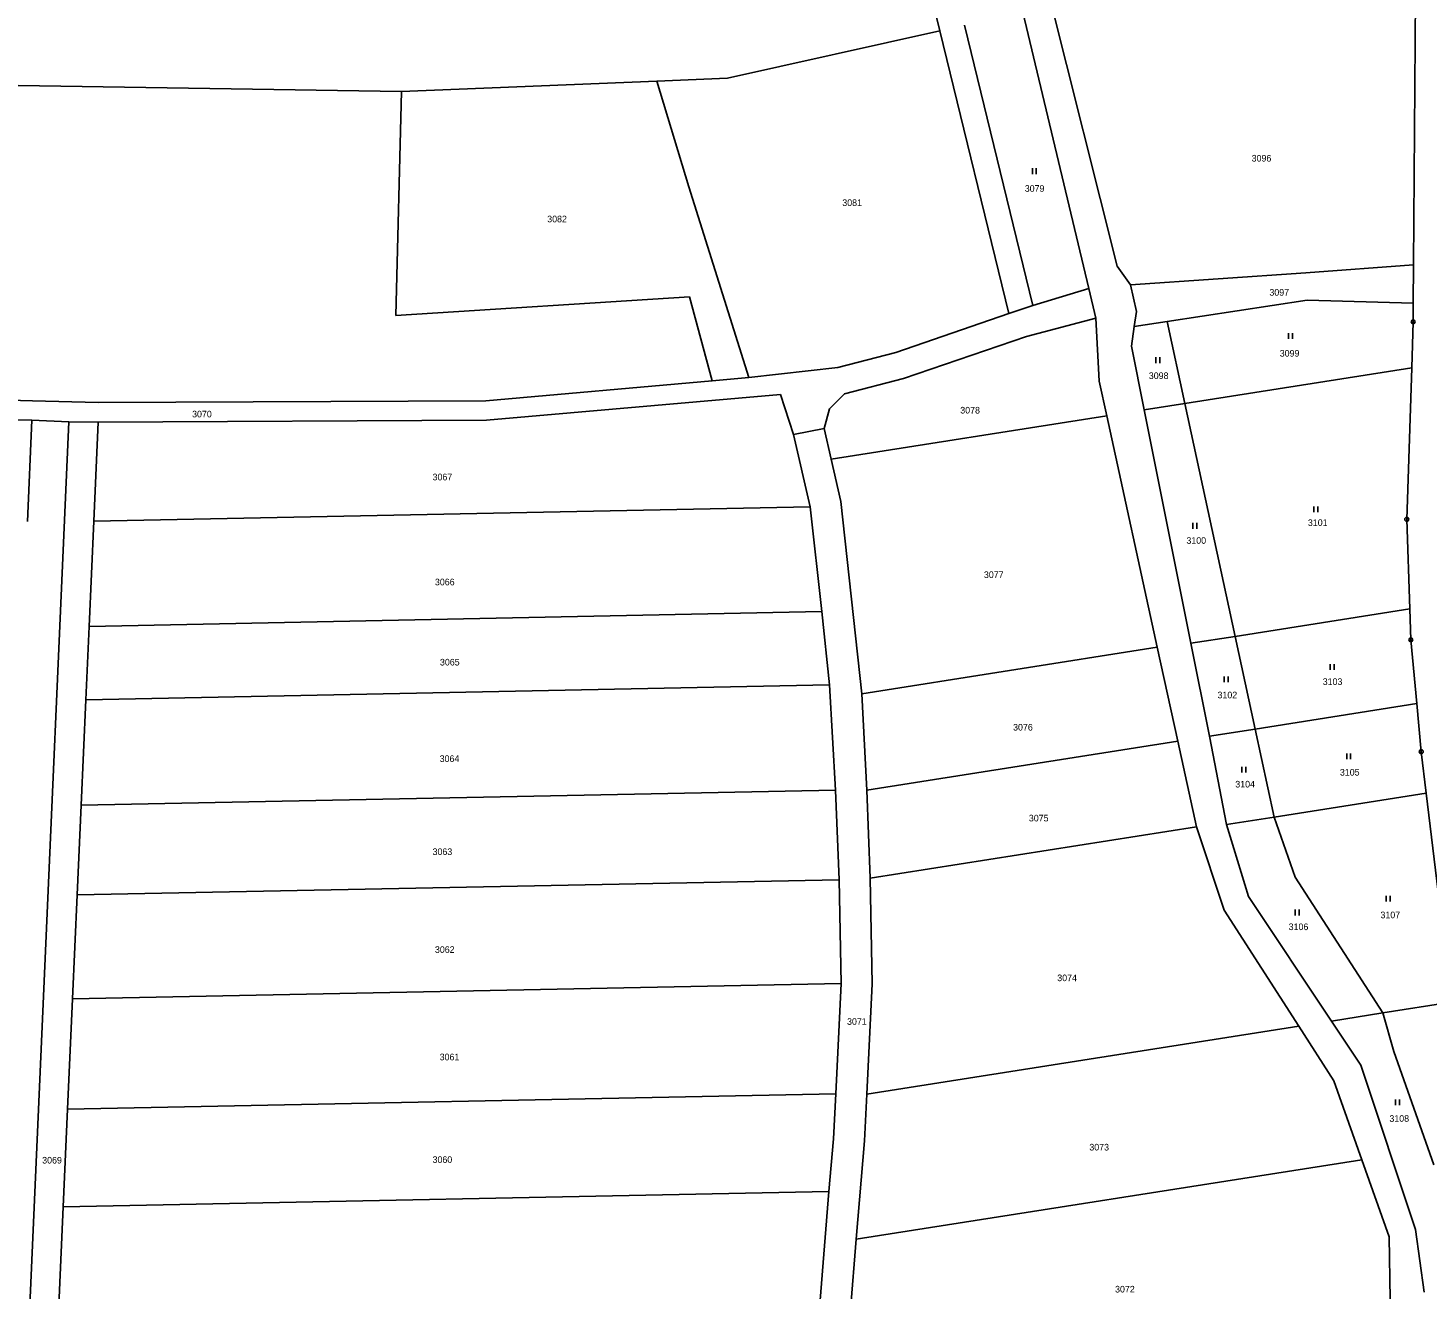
# Model space of a CAD drawing. Extents: x -618848 to -615803, y -1044450 to -1042254.
# Drawn here: x -617398.4 to -617038.7, y -1042756.5 to -1042432.5 of the extents above; entities that cross this region are included whole.
import ezdxf

# ---------------------------------------------------------------- set-up
doc = ezdxf.new("R2010")
doc.units = 0
doc.header["$LTSCALE"] = 0.68
for name, color, linetype, lineweight in [('1', 7, 'Continuous', 25), ('3', 7, 'Continuous', 25), ('8', 7, 'Continuous', 25)]:
    doc.layers.add(name, color=color, linetype=linetype, lineweight=lineweight)
doc.layers.add('2', color=7, linetype='Continuous')

msp = doc.modelspace()

# ---------------------------------------------------------------- linework, layer by layer
at = {"layer": '1'}
for p, q in [((-617164.1, -1042433.17), (-617176, -1042384.38)), ((-617041.82, -1042420.28), (-617042.37, -1042493.33)), ((-617136.12, -1042423.72), (-617118.55, -1042493.62)), ((-617157.76, -1042431.75), (-617140.2, -1042503.76)), ((-617125.82, -1042499.42), (-617142.76, -1042428.39)), ((-617218.65, -1042445.37), (-617164.1, -1042433.17)), ((-617146.38, -1042505.85), (-617164.1, -1042433.17)), ((-617302.39, -1042448.75), (-617236.84, -1042446.1)), ((-617236.84, -1042446.1), (-617218.65, -1042445.37)), ((-617236.84, -1042446.1), (-617228.59, -1042473.3)), ((-617465.98, -1042446.3), (-617302.39, -1042448.75)), ((-617303.82, -1042506.31), (-617302.39, -1042448.75)), ((-617228.59, -1042473.3), (-617213.14, -1042522.3)), ((-617118.55, -1042493.62), (-617115.07, -1042498.46)), ((-617115.07, -1042498.46), (-617070.06, -1042495.35)), ((-617070.06, -1042495.35), (-617042.37, -1042493.33)), ((-617042.37, -1042493.33), (-617042.45, -1042503.13)), ((-617140.2, -1042503.76), (-617125.82, -1042499.42)), ((-617124, -1042506.99), (-617125.82, -1042499.42)), ((-617115.07, -1042498.46), (-617113.6, -1042505.32)), ((-617228.38, -1042501.51), (-617303.82, -1042506.31)), ((-617222.59, -1042523.13), (-617228.38, -1042501.51)), ((-617140.2, -1042503.76), (-617146.38, -1042505.85)), ((-617069.68, -1042502.39), (-617105.66, -1042507.88)), ((-617042.45, -1042503.13), (-617069.68, -1042502.39)), ((-617042.45, -1042503.13), (-617042.48, -1042507.96)), ((-617175.43, -1042515.81), (-617146.38, -1042505.85)), ((-617141.86, -1042511.7), (-617124, -1042506.99)), ((-617123.16, -1042523.22), (-617124, -1042506.99)), ((-617113.6, -1042505.32), (-617114.15, -1042509.18)), ((-617114.15, -1042509.18), (-617114.86, -1042514.19)), ((-617105.66, -1042507.88), (-617114.15, -1042509.18)), ((-617101.11, -1042528.93), (-617105.66, -1042507.88)), ((-617042.48, -1042507.96), (-617042.86, -1042519.77)), ((-617173.41, -1042522.51), (-617141.86, -1042511.7)), ((-617114.86, -1042514.19), (-617111.59, -1042530.58)), ((-617190.33, -1042519.7), (-617175.43, -1042515.81)), ((-617213.14, -1042522.3), (-617190.33, -1042519.7)), ((-617101.11, -1042528.93), (-617042.86, -1042519.77)), ((-617042.86, -1042519.77), (-617044.13, -1042558.72)), ((-617222.59, -1042523.13), (-617280.75, -1042528.24)), ((-617213.14, -1042522.3), (-617222.59, -1042523.13)), ((-617188.56, -1042526.47), (-617173.41, -1042522.51)), ((-617121.22, -1042532.1), (-617123.16, -1042523.22)), ((-617397.22, -1042528.23), (-617515.35, -1042525.72)), ((-617380.36, -1042528.71), (-617397.22, -1042528.23)), ((-617280.75, -1042528.24), (-617380.36, -1042528.71)), ((-617280.52, -1042533.23), (-617205.06, -1042526.61)), ((-617205.06, -1042526.61), (-617201.67, -1042536.89)), ((-617192.45, -1042530.32), (-617188.56, -1042526.47)), ((-617111.59, -1042530.58), (-617101.11, -1042528.93)), ((-617088.23, -1042588.79), (-617101.11, -1042528.93)), ((-617497.67, -1042531.09), (-617397.33, -1042533.23)), ((-617193.81, -1042535.4), (-617192.45, -1042530.32)), ((-617121.22, -1042532.1), (-617192.03, -1042543.23)), ((-617108.24, -1042591.6), (-617121.22, -1042532.1)), ((-617111.59, -1042530.58), (-617099.62, -1042590.58)), ((-617397.33, -1042533.23), (-617398.46, -1042559.28)), ((-617397.33, -1042533.23), (-617387.84, -1042533.65)), ((-617394.98, -1042694.91), (-617387.84, -1042533.65)), ((-617387.84, -1042533.65), (-617380.34, -1042533.71)), ((-617381.47, -1042559.16), (-617380.34, -1042533.71)), ((-617380.34, -1042533.71), (-617280.52, -1042533.23)), ((-617201.67, -1042536.89), (-617193.81, -1042535.4)), ((-617192.03, -1042543.23), (-617193.81, -1042535.4)), ((-617201.67, -1042536.89), (-617197.44, -1042555.47)), ((-617192.03, -1042543.23), (-617189.55, -1042554.13)), ((-617189.55, -1042554.13), (-617184.17, -1042603.54)), ((-617197.44, -1042555.47), (-617381.47, -1042559.16)), ((-617194.37, -1042582.43), (-617197.44, -1042555.47)), ((-617381.47, -1042559.16), (-617382.67, -1042586.22)), ((-617044.13, -1042558.72), (-617043.35, -1042581.72)), ((-617382.67, -1042586.22), (-617194.37, -1042582.43)), ((-617194.37, -1042582.43), (-617192.47, -1042601.23)), ((-617043.35, -1042581.72), (-617088.23, -1042588.79)), ((-617043.35, -1042581.72), (-617043.08, -1042589.68)), ((-617383.51, -1042605.06), (-617382.67, -1042586.22)), ((-617099.62, -1042590.58), (-617088.23, -1042588.79)), ((-617083.1, -1042612.6), (-617088.23, -1042588.79)), ((-617043.08, -1042589.68), (-617041.55, -1042606.07)), ((-617184.17, -1042603.54), (-617108.24, -1042591.6)), ((-617102.98, -1042615.74), (-617108.24, -1042591.6)), ((-617099.62, -1042590.58), (-617094.85, -1042614.46)), ((-617192.47, -1042601.23), (-617383.51, -1042605.06)), ((-617190.9, -1042628.33), (-617192.47, -1042601.23)), ((-617184.17, -1042603.54), (-617182.86, -1042628.29)), ((-617383.51, -1042605.06), (-617384.7, -1042632.21)), ((-617083.1, -1042612.6), (-617041.55, -1042606.07)), ((-617041.55, -1042606.07), (-617040.41, -1042618.43)), ((-617094.85, -1042614.46), (-617083.1, -1042612.6)), ((-617094.85, -1042614.46), (-617090.4, -1042637.17)), ((-617078.2, -1042635.26), (-617083.1, -1042612.6)), ((-617182.86, -1042628.29), (-617102.98, -1042615.74)), ((-617098.18, -1042637.73), (-617102.98, -1042615.74)), ((-617040.41, -1042618.43), (-617039.11, -1042629.12)), ((-617384.7, -1042632.21), (-617190.9, -1042628.33)), ((-617190.9, -1042628.33), (-617189.97, -1042651.34)), ((-617181.99, -1042650.9), (-617182.86, -1042628.29)), ((-617078.2, -1042635.26), (-617039.11, -1042629.12)), ((-617039.11, -1042629.12), (-617034.33, -1042668.64)), ((-617385.72, -1042655.25), (-617384.7, -1042632.21)), ((-617090.4, -1042637.17), (-617078.2, -1042635.26)), ((-617072.82, -1042650.69), (-617078.2, -1042635.26)), ((-617098.18, -1042637.73), (-617181.99, -1042650.9)), ((-617091.04, -1042659.17), (-617098.18, -1042637.73)), ((-617090.4, -1042637.17), (-617084.8, -1042655.62)), ((-617181.99, -1042650.9), (-617181.48, -1042678.1)), ((-617050.29, -1042685.56), (-617072.82, -1042650.69)), ((-617189.97, -1042651.34), (-617385.72, -1042655.25)), ((-617189.48, -1042677.98), (-617189.97, -1042651.34)), ((-617385.72, -1042655.25), (-617386.91, -1042681.95)), ((-617084.8, -1042655.62), (-617063.5, -1042687.65)), ((-617071.86, -1042688.97), (-617091.04, -1042659.17)), ((-617386.91, -1042681.95), (-617189.48, -1042677.98)), ((-617189.48, -1042677.98), (-617190.81, -1042706.35)), ((-617181.48, -1042678.1), (-617182.81, -1042706.4)), ((-617388.17, -1042710.32), (-617386.91, -1042681.95)), ((-617032.7, -1042682.79), (-617050.29, -1042685.56)), ((-617063.5, -1042687.65), (-617050.29, -1042685.56)), ((-617050.29, -1042685.56), (-617047.48, -1042695.46)), ((-617182.81, -1042706.4), (-617071.86, -1042688.97)), ((-617062.85, -1042702.99), (-617071.86, -1042688.97)), ((-617055.97, -1042698.96), (-617063.5, -1042687.65)), ((-617402.12, -1042856.16), (-617394.98, -1042694.91)), ((-617047.48, -1042695.46), (-617037.18, -1042724.56)), ((-617041.88, -1042741.18), (-617055.97, -1042698.96)), ((-617055.65, -1042723.3), (-617062.85, -1042702.99)), ((-617190.81, -1042706.35), (-617388.17, -1042710.32)), ((-617191.45, -1042717.89), (-617190.81, -1042706.35)), ((-617182.81, -1042706.4), (-617183.47, -1042718.44)), ((-617388.17, -1042710.32), (-617389.28, -1042735.4)), ((-617192.57, -1042731.45), (-617191.45, -1042717.89)), ((-617183.47, -1042718.44), (-617185.57, -1042743.7)), ((-617185.57, -1042743.7), (-617055.65, -1042723.3)), ((-617048.67, -1042743.07), (-617055.65, -1042723.3)), ((-617389.28, -1042735.4), (-617192.57, -1042731.45)), ((-617192.57, -1042731.45), (-617194.86, -1042759.38)), ((-617391.24, -1042779.61), (-617389.28, -1042735.4)), ((-617039.67, -1042757.28), (-617041.88, -1042741.18)), ((-617185.57, -1042743.7), (-617187.04, -1042761.82)), ((-617048.38, -1042759.16), (-617048.67, -1042743.07))]:
    msp.add_line(p, q, dxfattribs=at)
at = {"layer": '3'}
for p, q in [((-617140.311, -1042470.01), (-617140.311, -1042468.51)), ((-617139.31, -1042470.01), (-617139.31, -1042468.51)), ((-617074.481, -1042512.35), (-617074.481, -1042510.85)), ((-617073.48, -1042512.35), (-617073.48, -1042510.85)), ((-617108.571, -1042518.58), (-617108.571, -1042517.08)), ((-617107.57, -1042518.58), (-617107.57, -1042517.08)), ((-617068.011, -1042556.88), (-617068.011, -1042555.38)), ((-617067.01, -1042556.88), (-617067.01, -1042555.38)), ((-617099.061, -1042561.12), (-617099.061, -1042559.62)), ((-617098.06, -1042561.12), (-617098.06, -1042559.62)), ((-617063.791, -1042597.42), (-617063.791, -1042595.92)), ((-617062.79, -1042597.42), (-617062.79, -1042595.92)), ((-617091.001, -1042600.6), (-617091.001, -1042599.1)), ((-617090, -1042600.6), (-617090, -1042599.1)), ((-617059.561, -1042620.35), (-617059.561, -1042618.85)), ((-617058.56, -1042620.35), (-617058.56, -1042618.85)), ((-617086.511, -1042623.79), (-617086.511, -1042622.29)), ((-617085.51, -1042623.79), (-617085.51, -1042622.29)), ((-617049.391, -1042656.93), (-617049.391, -1042655.43)), ((-617048.39, -1042656.93), (-617048.39, -1042655.43)), ((-617072.771, -1042660.5), (-617072.771, -1042659)), ((-617071.77, -1042660.5), (-617071.77, -1042659)), ((-617047.011, -1042709.27), (-617047.011, -1042707.77)), ((-617046.01, -1042709.27), (-617046.01, -1042707.77))]:
    msp.add_line(p, q, dxfattribs=at)
at = {"layer": '8'}
for centre, radius in [((-617042.48, -1042507.9599), 0.5), ((-617042.48, -1042507.9599), 0.0303), ((-617044.13, -1042558.7199), 0.5), ((-617044.13, -1042558.7199), 0.0303), ((-617043.08, -1042589.6799), 0.5), ((-617043.08, -1042589.6799), 0.0303), ((-617040.41, -1042618.4299), 0.5), ((-617040.41, -1042618.4299), 0.0303)]:
    msp.add_circle(centre, radius, dxfattribs=at)

# ---------------------------------------------------------------- texts
at = {"layer": '2'}
for s, p in [('3096', (-617083.98, -1042466.775)), ('3079', (-617142.27, -1042474.545)), ('3081', (-617189.15, -1042478.205)), ('3082', (-617264.96, -1042482.395)), ('3097', (-617079.42, -1042501.245)), ('3099', (-617076.76, -1042516.905)), ('3098', (-617110.4, -1042522.665)), ('3070', (-617356.2, -1042532.525)), ('3078', (-617158.84, -1042531.525)), ('3067', (-617294.42, -1042548.695)), ('3101', (-617069.53, -1042560.425)), ('3100', (-617100.74, -1042565.005)), ('3077', (-617152.77, -1042573.795)), ('3066', (-617293.81, -1042575.675)), ('3065', (-617292.52, -1042596.275)), ('3103', (-617065.72, -1042601.275)), ('3102', (-617092.75, -1042604.715)), ('3076', (-617145.27, -1042612.995)), ('3064', (-617292.59, -1042621.065)), ('3104', (-617088.18, -1042627.625)), ('3105', (-617061.31, -1042624.565)), ('3075', (-617141.22, -1042636.345)), ('3063', (-617294.42, -1042644.985)), ('3107', (-617050.88, -1042661.225)), ('3106', (-617074.47, -1042664.275)), ('3062', (-617293.81, -1042670.125)), ('3074', (-617133.92, -1042677.395)), ('3071', (-617187.93, -1042688.605)), ('3061', (-617292.59, -1042697.725)), ('3108', (-617048.59, -1042713.535)), ('3073', (-617125.68, -1042720.905)), ('3069', (-617394.71, -1042724.255)), ('3060', (-617294.42, -1042724.105)), ('3072', (-617119.07, -1042757.395))]:
    msp.add_text(s, height=1.7, dxfattribs=at).set_placement(p)

doc.saveas('drawing.dxf')
